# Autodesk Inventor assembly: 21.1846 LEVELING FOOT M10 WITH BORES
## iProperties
Created: 2007-03
Part Number: 21.1846 LEVELING FOOT M10 WITH BORES
Document SubType Name: Assembly
Designer: Andy Moles
Author: Andy Moles
